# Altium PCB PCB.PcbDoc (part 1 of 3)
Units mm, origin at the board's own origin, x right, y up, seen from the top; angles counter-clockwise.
Board outline 43.18 x 22.86 mm, 6 copper layers (TOP, L2_GND, L3_SIG, L4_PWR, L5_GND, BOTTOM), stack 1.573 mm thick; 127 components, 116 nets, 532 pads, 386 vias.
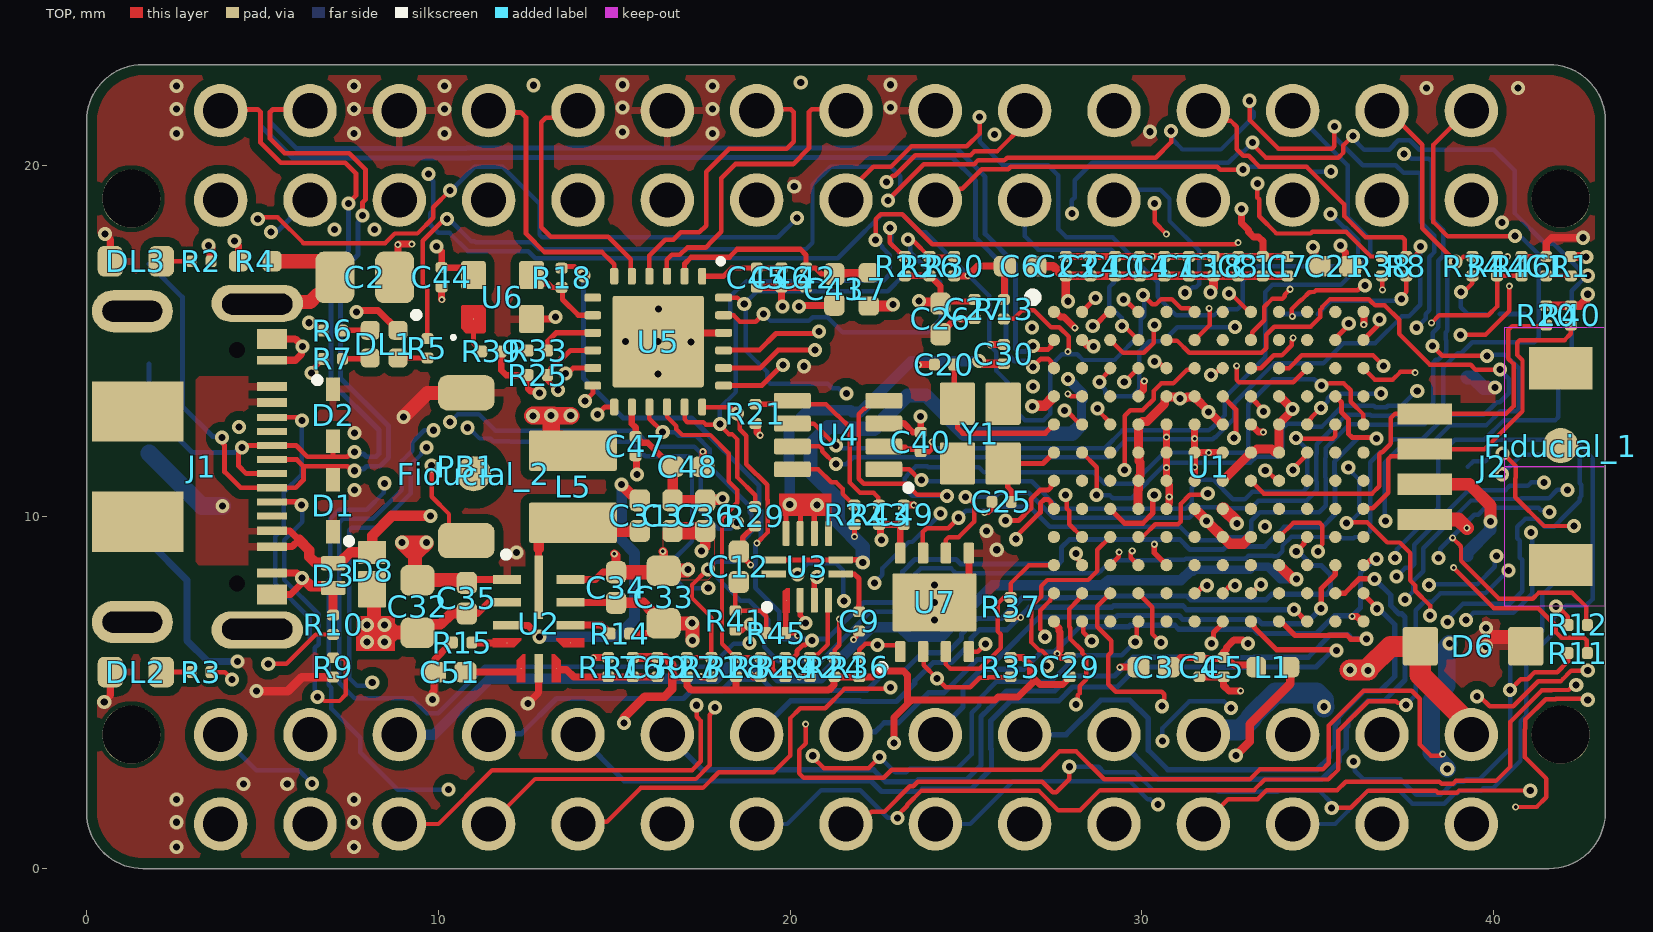
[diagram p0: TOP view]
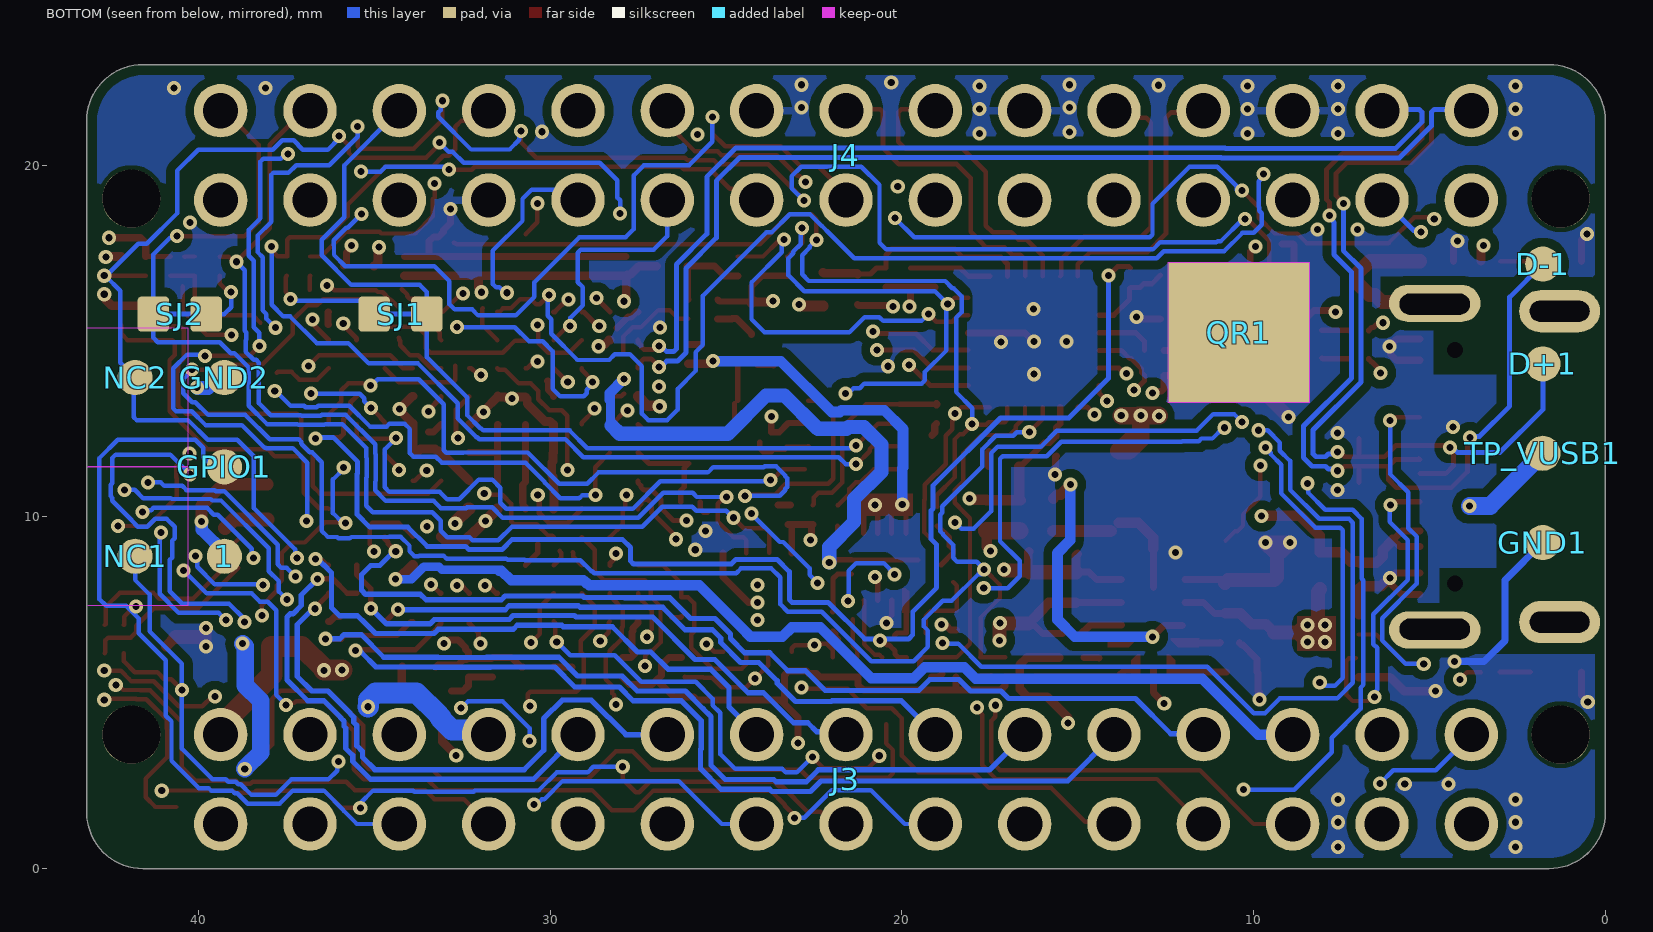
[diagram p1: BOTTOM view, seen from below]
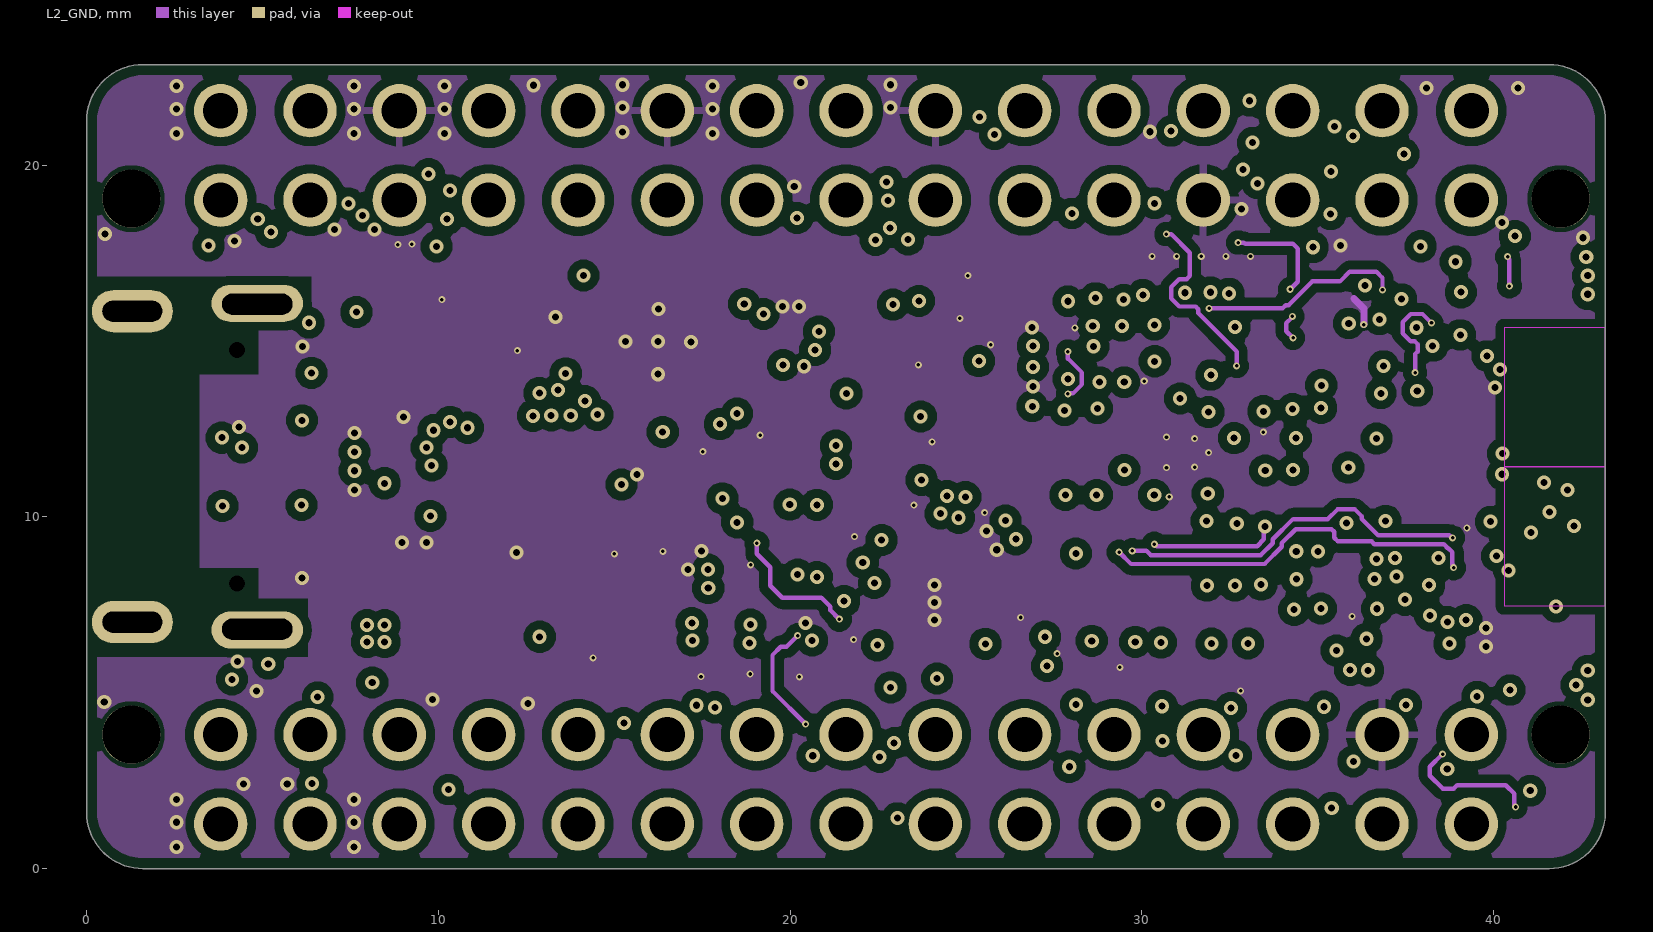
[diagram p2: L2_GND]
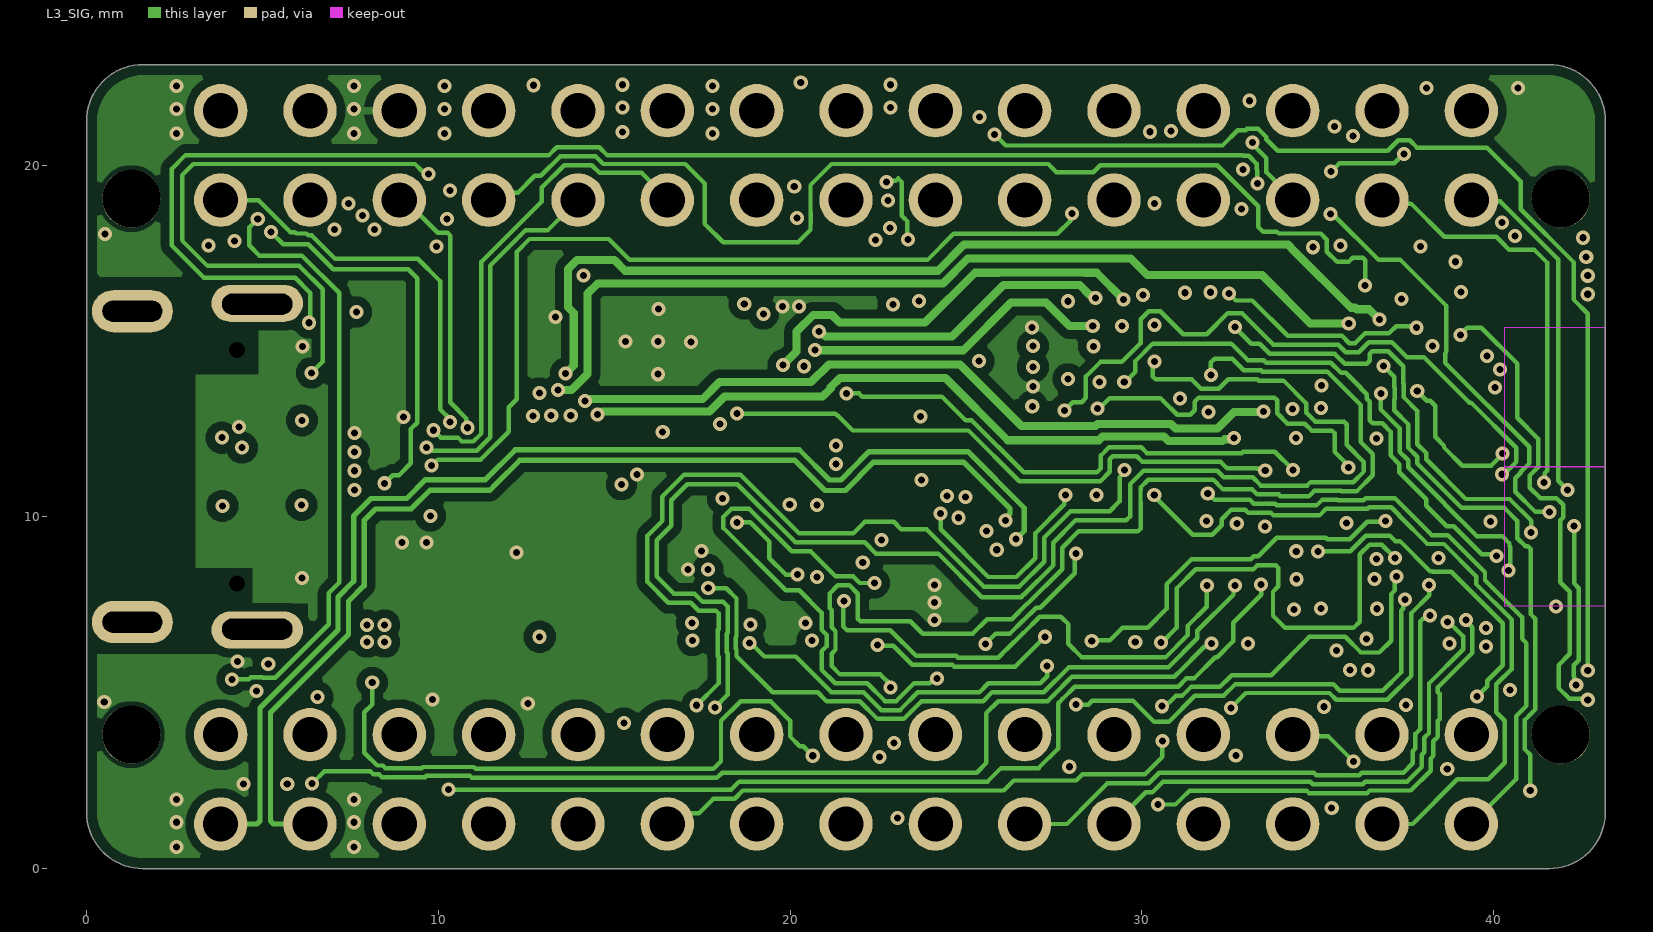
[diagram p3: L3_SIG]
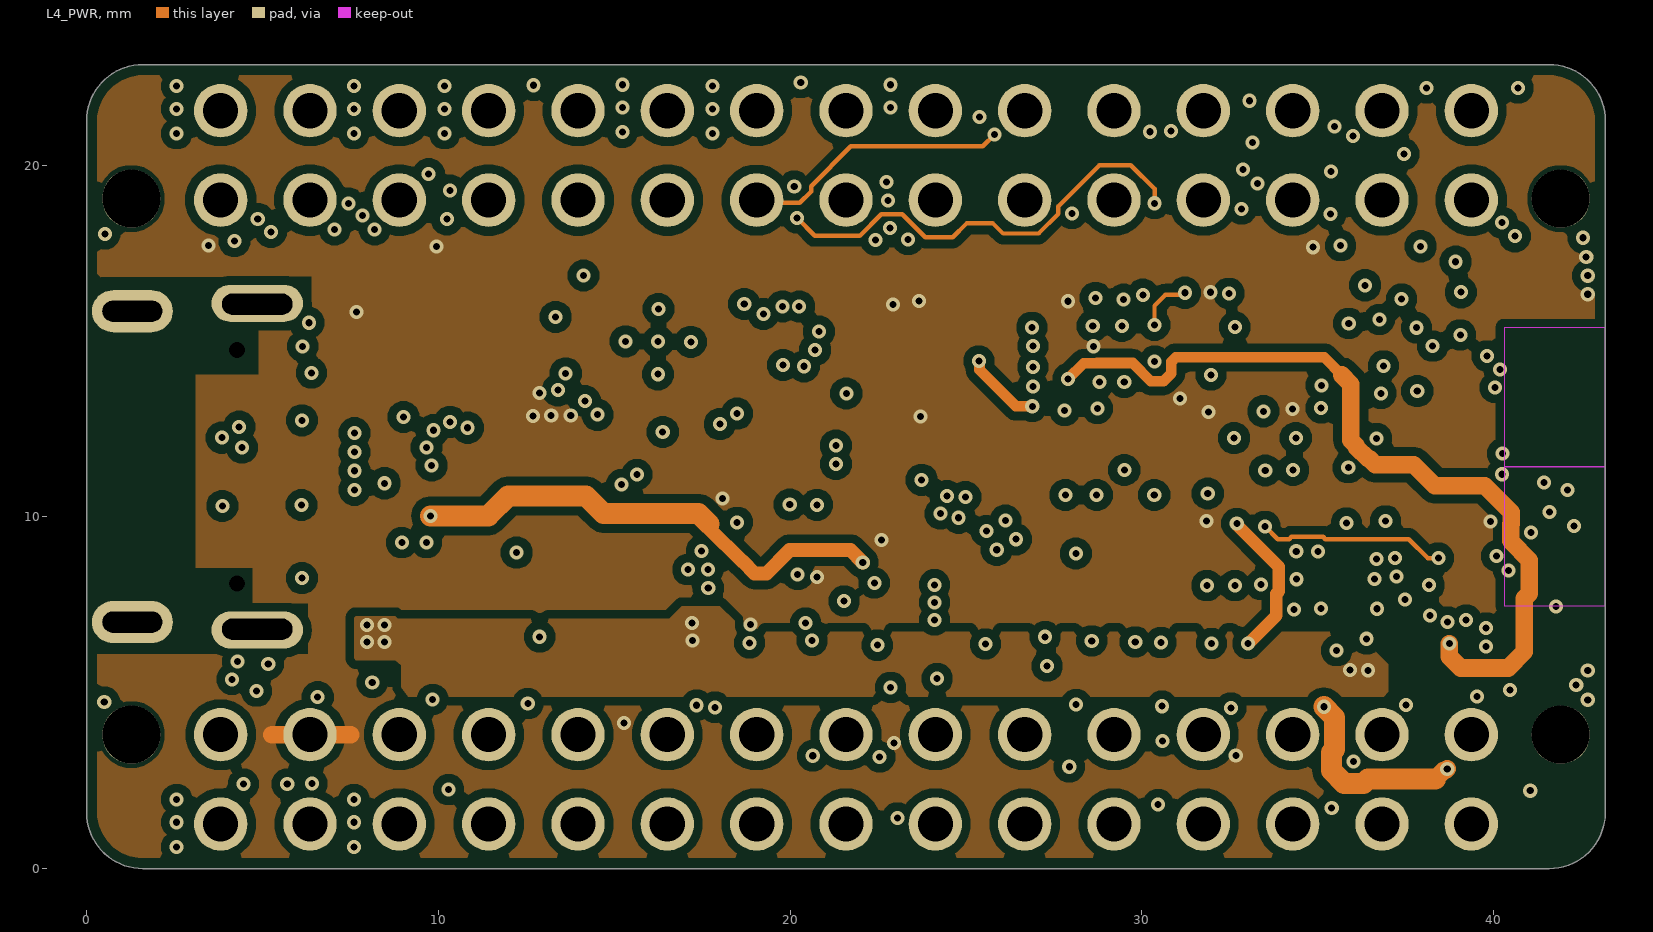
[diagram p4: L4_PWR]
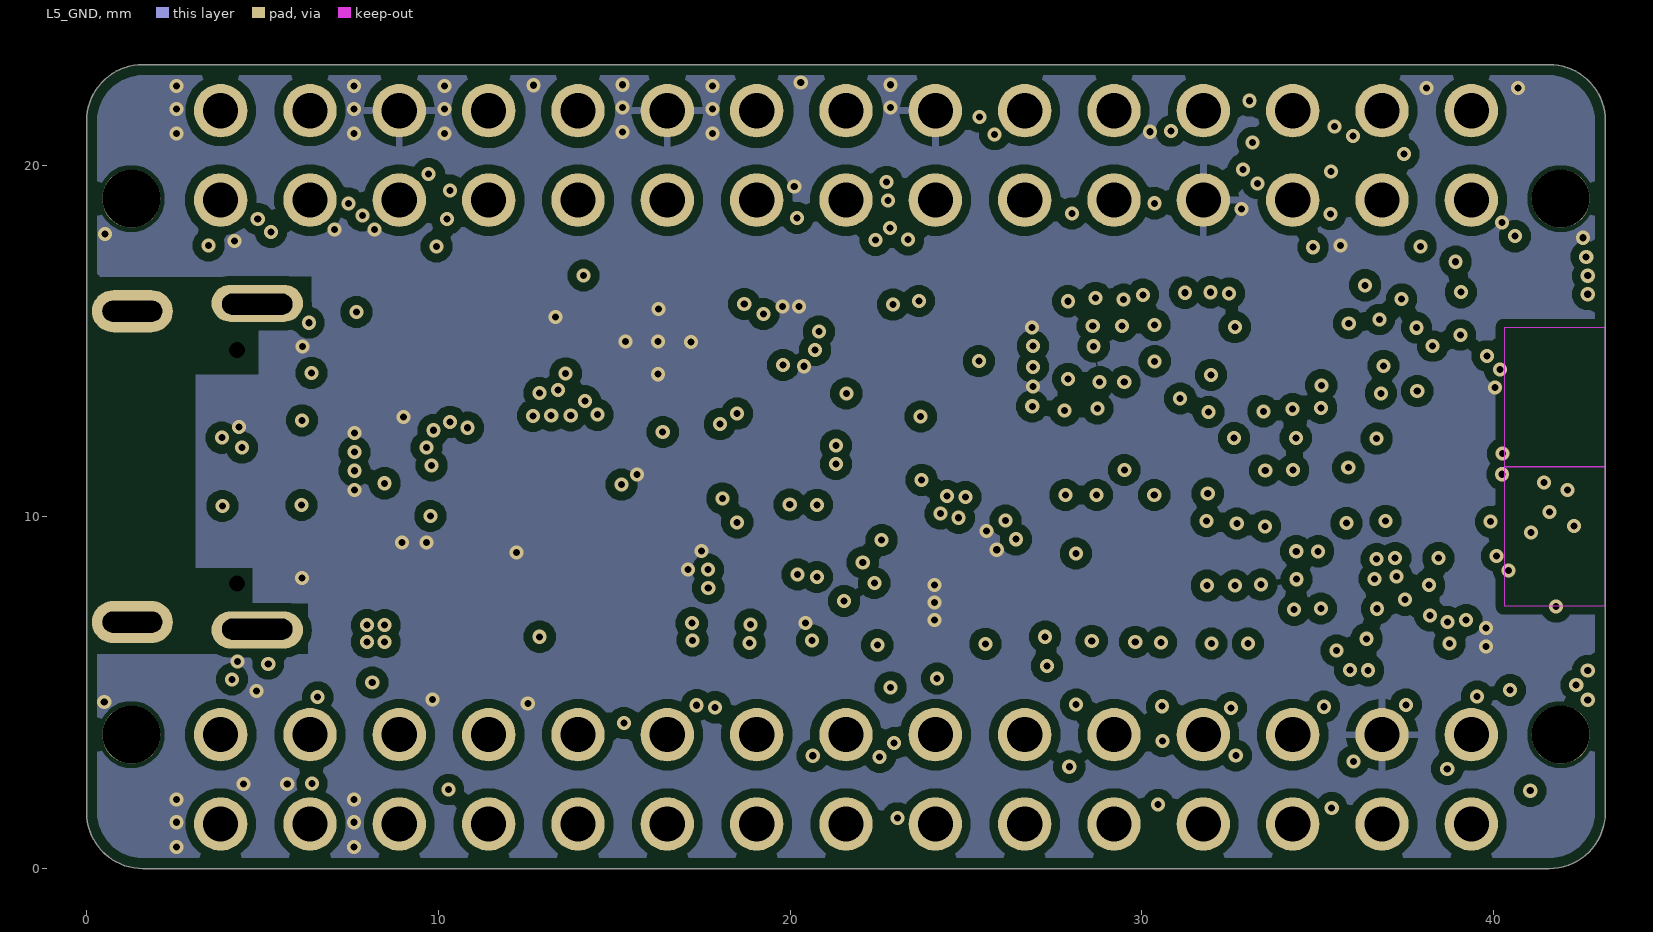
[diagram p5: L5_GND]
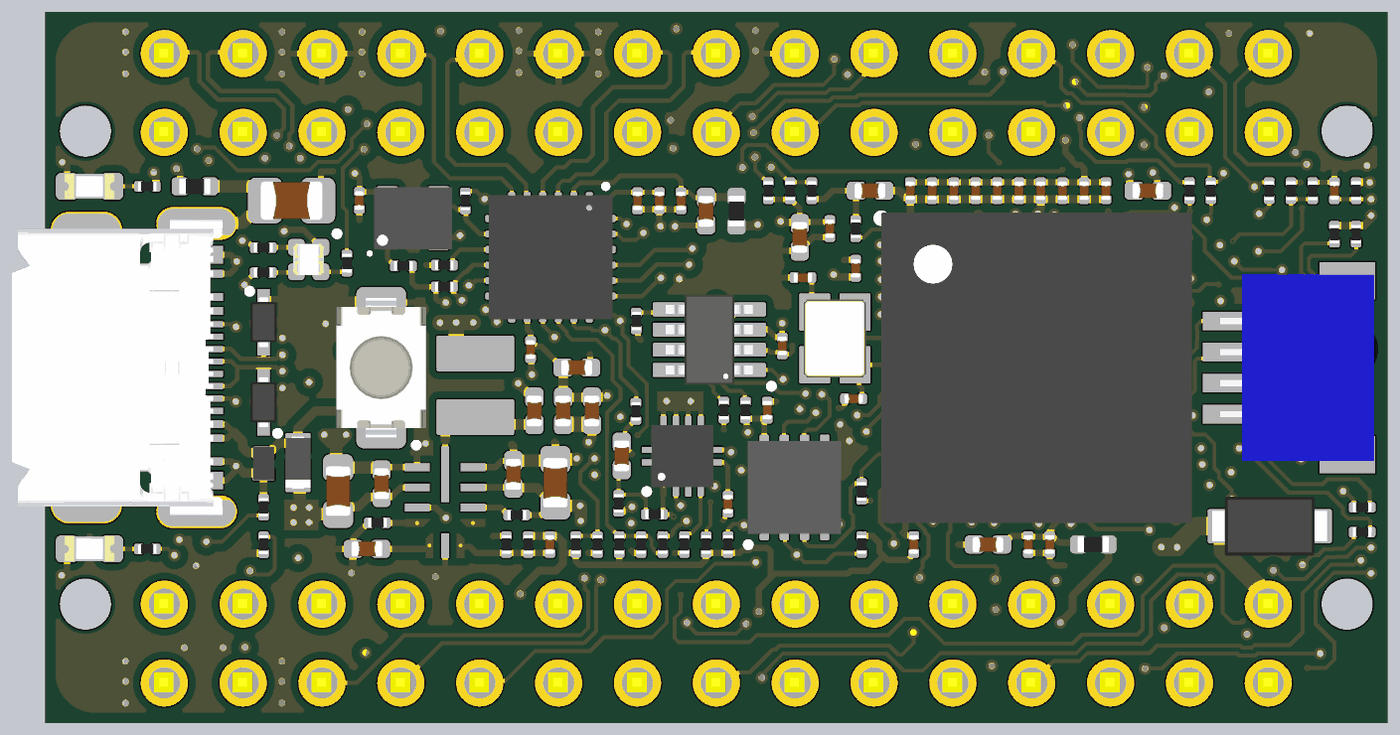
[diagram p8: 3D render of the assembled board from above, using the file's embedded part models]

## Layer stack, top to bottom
Top Solder: solder mask 0.0102, Solder Resist, Dk 3.5
TOP: signal copper 0.0175
Dielectric 1: prepreg 0.08, PP-008, Dk 4.1
L2_GND: signal copper 0.0175
Dielectric 4: core 0.55, Core-037, Dk 4.8
L3_SIG: signal copper 0.0175
Dielectric 2: prepreg 0.2083, PP-022, Dk 4.5
L4_PWR: signal copper 0.0175
Dielectric 5: core 0.55, Core-037, Dk 4.8
L5_GND: signal copper 0.0175
Dielectric 3: prepreg 0.08, PP-008, Dk 4.1
BOTTOM: signal copper 0.0175
Board Layer Stack Bottom Solder: solder mask 0.0102, Solder Resist, Dk 3.5

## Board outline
1.6,0 cw(c1.6,1.6) 0,1.6 0,21.26 cw(c1.6,21.26) 1.6,22.86 41.58,22.86 cw(c41.58,21.26) 43.18,21.26 43.18,1.6 cw(c41.58,1.6) 41.58,0

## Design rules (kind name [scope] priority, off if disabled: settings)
BoardOutlineClearance BoardOutlineClearance_2 [Component = 'J1'] p1: gap=0.1 ignorepadtopadclearanceinfootprint=FALSE
BoardOutlineClearance BoardOutlineClearance_1 [(ObjectKind = 'Pad') And (Name = 'Free-2') And (PadShape_AllLayers = 'Rounded Rectangle') And (AsMM(PadXSize_AllLayers) = 1.3) And (AsMM(PadYSize_AllLayers) = 1.8)] p2: gap=0.1 ignorepadtopadclearanceinfootprint=FALSE
BoardOutlineClearance HeadersCastellated [((ObjectKind = 'Pad') And (Component = 'JP1')) OR                                                                                    ((ObjectKind = 'Pad') And (Component = 'JP2'))] p3: gap=0 ignorepadtopadclearanceinfootprint=FALSE
BoardOutlineClearance Silks [(OnLayer('Top Overlay') OR OnLayer('Bottom Overlay'))] p4: gap=0 ignorepadtopadclearanceinfootprint=FALSE
BoardOutlineClearance [All] p5: gap=0.3 ignorepadtopadclearanceinfootprint=FALSE
Clearance GND_50R [InNetClass('50R') vs InNet('GND')] p1: gap=0.127 ignorepadtopadclearanceinfootprint=FALSE
Clearance GND_ETH [InDifferentialPairClass('ETH') vs InNet('GND')] p2: gap=0.3 ignorepadtopadclearanceinfootprint=TRUE
Clearance QR [InComponent('QR1') vs InNet('GND')] p3: gap=0.15 ignorepadtopadclearanceinfootprint=FALSE except(0: Arc-SMDPad Arc-Fill Arc-Poly Arc-Region Track-SMDPad Track-Fill Track-Poly Track-Region SMDPad-SMDPad SMDPad-Fill SMDPad-Poly SMDPad-Region THPad-Fill THPad-Poly THPad-Region Via-Fill Via-Poly Via-Region Fill-Fill Fill-Poly Fill-Region Poly-Poly Poly-Region Region-Region)
Clearance COPPER_0.25mm [All] p4: gap=0.127 ignorepadtopadclearanceinfootprint=FALSE except(0.25: Arc-Fill Arc-Poly Arc-Region Track-Fill Track-Poly Track-Region SMDPad-Fill SMDPad-Poly SMDPad-Region THPad-Fill THPad-Poly THPad-Region Via-Fill Via-Poly Via-Region Fill-Fill Fill-Poly Fill-Region Poly-Poly Poly-Region Region-Region)
Clearance "Generic clearance 0.127mm" [All] p5: gap=0.127 ignorepadtopadclearanceinfootprint=TRUE
ComponentClearance TP2 [((Name = 'MTDI') OR (Name = 'MTDO') OR (Name = 'MTCK') OR (Name = 'MTMS'))] p1: gap=-2 collisioncheckmode=3 verticalgap=0 showdistances=FALSE
ComponentClearance TP [HasFootprint('TP-1.00MM') vs HasFootprint('TP-1.00MM')] p2: gap=0.2 collisioncheckmode=3 verticalgap=-10 showdistances=FALSE
ComponentClearance UFL_ANTENNA [InComponent('ANT1') vs HasFootprint('U.FL-R-SMT-1(60)-1')] p3: gap=-20 collisioncheckmode=3 verticalgap=-20 showdistances=FALSE
ComponentClearance Headers [((Footprint = 'PINHD-1X14_5VF') OR (Footprint = 'PINHD-1X14_5VF') OR (Footprint = 'LEDC1608X80N-AK') OR (Footprint = 'CX90B-16P-Footprint-1') ) vs ((Footprint = 'PINHD-1X14_5VF') OR (Footprint = 'PINHD-1X14_5VF') OR (Footprint = 'LEDC1608X80N-AK') OR (Footprint = 'CX90B-16P-Footprint-1'))] p4: gap=-20 collisioncheckmode=3 verticalgap=-20 showdistances=FALSE
ComponentClearance RFshield [HasFootprint('Shield RF 10mm x 15mm x 3mm-Footprint-1')] p5: gap=-50 collisioncheckmode=3 verticalgap=-20 showdistances=FALSE
ComponentClearance fiducials [InComponent('Fiducial_1') vs InComponent('PB1')] p6: gap=-20 collisioncheckmode=3 verticalgap=-20 showdistances=FALSE
ComponentClearance [All] p7: gap=0.2 collisioncheckmode=3 verticalgap=0 showdistances=TRUE
DiffPairsRouting USB [InDifferentialPairClass('USB')] p1: maxlimit=0.25 minlimit=0.13 mostfreqgap=0.15 toplayer_maxgap=0.13 toplayer_prefgap=0.13 toplayer_minwidth=0.14 toplayer_maxwidth=0.14 toplayer_prefwidth=0.14 midlayer2_mingap=0.15 midlayer2_maxgap=0.15 midlayer2_minwidth=0.15 midlayer2_maxwidth=0.15 midlayer2_prefwidth=0.15 midlayer3_mingap=0.15 midlayer3_maxgap=0.15 midlayer3_minwidth=0.15 midlayer3_maxwidth=0.15 midlayer3_prefwidth=0.15 bottomlayer_maxgap=0.13 bottomlayer_prefgap=0.13 bottomlayer_minwidth=0.14 bottomlayer_maxwidth=0.14 bottomlayer_prefwidth=0.14 impedanceprofiledriven=TRUE impedanceprofileid={80FA380A-D0E5-4DCC-A5FB-10CACAF929A0} impedanceprofilevalue=90.000000 maxuncoupledlength=12.7
DiffPairsRouting USB_FS [InDifferentialPairClass('USBC_FS')] p2: maxlimit=0.25 minlimit=0.13 mostfreqgap=0.15 toplayer_maxgap=0.13 toplayer_prefgap=0.13 toplayer_minwidth=0.14 toplayer_maxwidth=0.14 toplayer_prefwidth=0.14 midlayer2_mingap=0.15 midlayer2_maxgap=0.15 midlayer2_minwidth=0.15 midlayer2_maxwidth=0.15 midlayer2_prefwidth=0.15 midlayer3_mingap=0.15 midlayer3_maxgap=0.15 midlayer3_minwidth=0.15 midlayer3_maxwidth=0.15 midlayer3_prefwidth=0.15 bottomlayer_maxgap=0.13 bottomlayer_prefgap=0.13 bottomlayer_minwidth=0.14 bottomlayer_maxwidth=0.14 bottomlayer_prefwidth=0.14 impedanceprofiledriven=TRUE impedanceprofileid={80FA380A-D0E5-4DCC-A5FB-10CACAF929A0} impedanceprofilevalue=90.000000 maxuncoupledlength=12.7
DiffPairsRouting ETH [InDifferentialPairClass('ETH')] p3: maxlimit=0.3 minlimit=0.15 mostfreqgap=0.25 toplayer_mingap=0.3 toplayer_prefgap=0.3 toplayer_minwidth=0.133 toplayer_maxwidth=0.133 toplayer_prefwidth=0.133 midlayer2_mingap=0.218 midlayer2_maxgap=0.218 midlayer2_prefgap=0.218 midlayer2_minwidth=0.15 midlayer2_maxwidth=0.15 midlayer2_prefwidth=0.15 midlayer3_mingap=0.218 midlayer3_maxgap=0.218 midlayer3_prefgap=0.218 midlayer3_minwidth=0.15 midlayer3_maxwidth=0.15 midlayer3_prefwidth=0.15 bottomlayer_mingap=0.3 bottomlayer_prefgap=0.3 bottomlayer_minwidth=0.133 bottomlayer_maxwidth=0.133 bottomlayer_prefwidth=0.133 impedanceprofiledriven=TRUE impedanceprofileid={95B8D7AC-9C73-46F7-8235-481973D37AAE} impedanceprofilevalue=100.000000 maxuncoupledlength=12.7
Height [All] p1: minheight=0 maxheight=30 prefheight=12.7
HoleSize [All] p1: absolutevalues=TRUE maxlimit=30 minlimit=0.099 maxpercent=80.000 minpercent=20.000
HoleToHoleClearance [All] p1: gap=0.25 allowstackedmicrovias=FALSE
MatchedLengths RMII_TX [InNet('TXDI') AND InNet('TXD0')] p1: tolerance=1.25 checknetsindiffpair=FALSE checkdiffpairvsdiffpair=TRUE checkxsignals=TRUE checkothers=TRUE phasematching=TRUE phasetolerance=0.254 phasedistance=12.7
MatchedLengths RMII_RX [InNet('RXD1') AND InNet('RXD0')] p2: tolerance=1.25 checknetsindiffpair=FALSE checkdiffpairvsdiffpair=TRUE checkxsignals=TRUE checkothers=TRUE phasematching=TRUE phasetolerance=0.254 phasedistance=12.7
MatchedLengths ETH_intra [InDifferentialPairClass('ETH')] p3: tolerance=0.25 checknetsindiffpair=TRUE checkdiffpairvsdiffpair=FALSE checkxsignals=FALSE checkothers=FALSE phasematching=TRUE phasetolerance=0.254 phasedistance=12.7
MatchedLengths ETH_group [InDifferentialPairClass('ETH')] p4: tolerance=50 checknetsindiffpair=FALSE checkdiffpairvsdiffpair=TRUE checkxsignals=TRUE checkothers=TRUE
NetAntennae NetAntennae_SJ [InComponent('SJ1') OR InComponent('SJ2')] p1: netantennaetolerance=1
NetAntennae [All] p2: netantennaetolerance=0
PlaneConnect [All] p1: pad.planeconnectstyle=Relief pad.reliefexpansion=0.508 pad.reliefentries=4 pad.reliefconductorwidth=0.15 pad.reliefairgap=0.254 via.planeconnectstyle=Direct via.reliefexpansion=0.508 via.reliefentries=4 via.reliefconductorwidth=0.254 via.reliefairgap=0.254
PolygonConnect 0201 [HasFootprint('RES-0201') OR HasFootprint('CAP-0201')] p1: connectstyle=Relief reliefconductorwidth=0.15 reliefentries=4 polygonreliefangle="90 Angle" airgapwidth=0.254
PolygonConnect PolygonConnect_QR [HasFootprint('QR CODE 4x4mm') vs InNet('GND')] p2: connectstyle=Direct reliefconductorwidth=0.2 reliefentries=4 polygonreliefangle="90 Angle" airgapwidth=0.254
PolygonConnect [All] p3: thpad.connectstyle=Relief thpad.reliefconductorwidth=0.2 thpad.reliefentries=4 thpad.polygonreliefangle="90 Angle" thpad.airgapwidth=0.254 smdpad.connectstyle=Relief smdpad.reliefconductorwidth=0.2 smdpad.reliefentries=4 smdpad.polygonreliefangle="90 Angle" smdpad.airgapwidth=0.254 via.connectstyle=Direct via.reliefconductorwidth=0.254 via.reliefentries=4 via.polygonreliefangle="90 Angle" via.airgapwidth=0.254
RoomDefinition TOP [InComponentClass('TOP')] p1: confinementstyle=ConfineIn formatcopy=TRUE lockcomponents=FALSE outline 44.6,5.14 48.6,5.14 48.6,8.14 44.6,8.14
RoutingVias BlindVias [IsBlindVia] p1: holewidth=0.1 width=0.2 viastyle="Through Hole" minholewidth=0.09 minwidth=0.19 maxholewidth=0.1 maxwidth=0.2
RoutingVias StandardVias [All] p2: holewidth=0.2 width=0.4 viastyle="Through Hole" minholewidth=0.2 minwidth=0.4 maxholewidth=0.2 maxwidth=0.4
ShortCircuit ShortCircuit_jumper1 [Component = 'SJ1' vs (InNet('CANL_1') OR InNet('NetR8_1'))] p1: allowed=TRUE
ShortCircuit ShortCircuit_jumper2 [Component = 'SJ2' vs (InNet('RS485 B_1') OR InNet('NetR34_1'))] p2: allowed=TRUE
ShortCircuit [Component = 'SJ1' vs (InNet('+3V3') OR InNet('NetC25_2'))] p3: allowed=TRUE
SilkToSilkClearance [All] p1: silktosilkclearance=0.2
SilkToSolderMaskClearance [IsPad] p1: minsilkscreentomaskgap=0.15 clearancetoexposedcopper=TRUE
SolderMaskExpansion VIAtented [IsVia] p1: expansion=0.102 istentingtop=TRUE
SolderMaskExpansion [All] p2: expansion=0.05 istentingtop=FALSE
SupplyNets "Schematic Supply Nets" [InNet('VIN')] p1: voltage=0.000
SupplyNets "Schematic Supply Nets_6" [InNet('+VBUS')] p2: voltage=0.000
SupplyNets "Schematic Supply Nets_3" [InNet('GND')] p3: voltage=0.000
SupplyNets "Schematic Supply Nets_1" [InNet('+3V3')] p4: voltage=0.000
UnConnectedPin [All] p1:
UnRoutedNet [All] p1: checkbadconnections=TRUE
ViasUnderSMD Flash [(ObjectKind = 'Pad') And (Name = 'U2-9')] p1: allowed=TRUE
ViasUnderSMD uC [(ObjectKind = 'Pad') And (Name = 'U4-49')] p2: allowed=TRUE
ViasUnderSMD [All] p3: allowed=FALSE
Width 50R [InNetClass('RMII')] p1: maxlimit=0.231 minlimit=0.099 preferedwidth=0.231 toplayer_minwidth=0.142 toplayer_maxwidth=0.142 toplayer_prefwidth=0.142 midlayer1_maxwidth=0.099 midlayer1_prefwidth=0.099 midlayer2_minwidth=0.231 midlayer3_minwidth=0.231 midlayer4_maxwidth=0.099 midlayer4_prefwidth=0.099 bottomlayer_minwidth=0.142 bottomlayer_maxwidth=0.142 bottomlayer_prefwidth=0.142 impedanceprofiledriven=TRUE impedanceprofileid={20FD7761-1233-4024-A355-2B769554217A} impedanceprofilevalue=50.000000 minimp=50.000000 maximp=50.000000 favimp=50.000000
Width StandardTraces [All] p2: maxlimit=5 minlimit=0.127 preferedwidth=0.15
19 further rules are at their usual default settings.

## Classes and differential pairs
differential pair class USB: USB_D_1
differential pair class ETH: ETH_RX_1 ETH_TX_1
differential pair class USBC_FS: USBFS_D
net class ETH: ETH_RX_1_N ETH_RX_1_P ETH_TX_1_N ETH_TX_1_P
net class RMII: MDC MDIO RXD0 RXD1 TXD0 TXDI TXEN
component class "U_UART - RS485": + C49 R35 R36 R37 U7
component class U_MICROCONTROLLER: C3 C4 C5 C6 C7 C8 C10 C11 C13 C14 C17 C18 C20 C21 C23 C24 C25 C26 C27 C29 L1 R11 R12 R13 U1 Y1
component class U_ETH_10_100: C42 C43 C44 C45 C46 C47 C48 L7 R23 R24 R25 R26 R27 R28 R29 R30 R31 R32 R33 R39 U5 U6
component class U_CAN_PHY: C40 R21 R22 R43 U4
component class TOP: 1 + C1 C2 C9 C12 C30 C31 C32 C33 C34 C35 C36 C37 C39 C51 D1 D2 D3 D6 D8 D+1 D-1 DL1 DL2 DL3 Fiducial_1 Fiducial_2 GND1 GND2 GPIO1 J1 J2 J3 J4 L5 NC1 NC2 PB1 QR1 R1 R2 R3 R4 R5 R6 R7 R8 R9 R10 R14 R15 R16 R17 R18 R19 R20 R34 R38 R40 R41 R42 R44 R45 R46 SJ1 SJ2 TP_VUSB1 U2 U3
differential pair USB_D_1: +USB_D_1_P -USB_D_1_N
differential pair ETH_TX_1: +ETH_TX_1_P -ETH_TX_1_N
differential pair ETH_RX_1: +ETH_RX_1_P -ETH_RX_1_N
differential pair USBFS_D: +USBFS_D_P -USBFS_D_N

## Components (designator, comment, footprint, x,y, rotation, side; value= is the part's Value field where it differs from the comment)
1 "Test point 1.00mm" TP-1.00MM 39.263,8.881 r270 bottom
C1 "CL03A104KP3NNNC" CAP-0201 41.5,17.131 r270 top value=100nF
C2 "FV21X472K102ECG" CAP-0805 7.908,16.813 r180 top value=4.7nF
C3 "CC0402KRX5R6BB475" CAP-0402 30.341,5.731 r0 top value=4.7µF
C4 "CL03A104KP3NNNC" CAP-0201 31.639,5.731 r90 top value=100nF
C5 "CL03B103KP3NNND" CAP-0201 32.329,5.731 r90 top value=10nF
C6 "GRM158R60J226ME01D" CAP-0402 26.541,17.131 r0 top value=22µF
C7 "CL03A104KP3NNNC" CAP-0201 34.141,17.131 r270 top value=100nF
C8 "CL03A104KP3NNNC" CAP-0201 32.741,17.131 r270 top value=100nF
C9 "CL03B103KP3NNND" CAP-0201 21.965,7.031 r270 top value=10nF
C10 "CL03B103KP3NNND" CAP-0201 29.241,17.131 r270 top value=10nF
C11 "CL03B103KP3NNND" CAP-0201 33.441,17.131 r270 top value=10nF
C12 "CC0402KRX5R6BB475" CAP-0402 18.544,8.586 r270 top value=4.7µF
C13 "CL03A104KP3NNNC" CAP-0201 31.341,17.131 r270 top value=100nF
C14 "CL03A104KP3NNNC" CAP-0201 29.941,17.131 r270 top value=100nF
C17 "CL03B103KP3NNND" CAP-0201 30.641,17.131 r270 top value=10nF
C18 "CL03B103KP3NNND" CAP-0201 32.041,17.131 r270 top value=10nF
C20 "CC0201GRNPO9BN100" CAP-0201 24.377,14.33 r180 top value=10pF
C21 "GRM158R60J226ME01D" CAP-0402 35.491,17.131 r180 top value=22µF
C23 "CL03A104KP3NNNC" CAP-0201 27.841,17.131 r270 top value=100nF
C24 "CL03B103KP3NNND" CAP-0201 28.541,17.131 r270 top value=10nF
C25 "CC0201GRNPO9BN100" CAP-0201 26.013,10.426 r180 top value=10pF
C26 "CC0402KRX5R6BB475" CAP-0402 24.277,15.63 r90 top value=4.7µF
C27 "CL03A104KP3NNNC" CAP-0201 25.245,15.909 r90 top value=100nF
C29 "CL03A104KP3NNNC" CAP-0201 27.949,5.731 r270 top value=100nF
C30 "CL03A104KP3NNNC" CAP-0201 26.077,14.63 r270 top value=100nF
C31 "GRM155R61H104KE19D" CAP-0402 15.728,10.037 r90 top value=100nF
C32 "GRM188R6YA475KE15D" CAP-0603 9.408,7.453 r270 top value=4.7µF
C33 "GRM188R6YA475KE15D" CAP-0603 16.407,7.722 r270 top value=4.7µF
C34 "GRM155R61H104KE19D" CAP-0402 15.053,7.993 r270 top value=100nF
C35 "GRM155R61H104KE19D" CAP-0402 10.809,7.691 r270 top value=100nF
C36 "CC0402KRX5R6BB475" CAP-0402 17.584,10.037 r90 top value=4.7µF
C37 "CC0402KRX5R6BB475" CAP-0402 16.656,10.037 r90 top value=4.7µF
C39 "CC0201JPNPO8BN220" CAP-0201 16.229,5.731 r90 top value=22pF
C40 "CL03A104KP3NNNC" CAP-0201 23.715,12.131 r90 top value=100nF
C42 "CL03A104KP3NNNC" CAP-0201 20.455,16.806 r90 top value=100nF
C43 "GRM158R60J226ME01D" CAP-0402 21.259,16.47 r90 top value=22µF
C44 "CL03A104KP3NNNC" CAP-0201 10.092,16.814 r90 top value=100nF
C45 "CL03A104KP3NNNC" CAP-0201 19.055,16.806 r90 top value=100nF
C46 "CM03X5R225M06AH" CAP-0201 19.755,16.806 r90 top value=2.2µF
C47 "CL03A104KP3NNNC" CAP-0201 15.608,12.013 r90 top value=100nF
C48 "GRM158R60J226ME01D" CAP-0402 17.096,11.43 r180 top value=22µF
C49 "CL03A104KP3NNNC" CAP-0201 23.232,10.06 r270 top value=100nF
C51 "C1005X5R1E105K050BC" CAP-0402 10.336,5.589 r0 top value=1µF
D1 "ESD321DYAR" ESD321DYAR 7.008,10.313 r270 top
D2 "ESD321DYAR" ESD321DYAR 7.008,12.892 r90 top
D3 "STN101050B301" X1-DFN1006-2 7.008,8.333 r270 top
D6 "SJD12C24L01" SOD123W_BIDIR 39.417,6.322 r180 top
D8 "TPMEG4020EPK" "DFN1608-2 TPMEG4020EPK" 8.115,8.469 r270 top
D+1 "Test point 1.00mm" TP-1.00MM 1.778,14.351 r180 bottom locked
D-1 "Test point 1.00mm" TP-1.00MM 1.778,17.191 r180 bottom locked
DL1 "LTST-C28NBEGK-2A" SMLP34RGB2W 8.458,14.913 r180 top
DL2 "LTST-C190KSKT" LEDC1608X80N-AK#1 1.4,5.59 r0 top
DL3 "LTST-C190KGKT" LEDC1608X80N-AK#2 1.4,17.27 r0 top
Fiducial_1 "Fiducial mark 1mm with 2mm solder" "Fiducial mark 1mm with circle-Footprint-1"#1 41.91,12.03 r90 top
Fiducial_2 "Fiducial mark 1mm with 2mm solder" "Fiducial mark 1mm with circle-Footprint-1"#2 11,11.23 r270 top
GND1 "Test point 1.00mm" TP-1.00MM 1.778,9.271 r90 bottom
GND2 "Test point 1.00mm" TP-1.00MM 39.263,13.961 r270 bottom
GPIO1 "Test point 1.00mm" TP-1.00MM 39.263,11.421 r90 bottom
J1 "CX90B-16P" CX90B-16P-Footprint-1 3.288,11.43 r270 top locked
J2 "SM04B-SRSS-TB(LF)(SN)" SM04B-SRSS-TB(LF)(SN)-Footprint-1 39.977,11.43 r270 top locked
J3 "2.54-2*15P" "PIN HEADER MALE 2.54mm VERT. 2x15POS" 21.57,2.56 r0 bottom locked
J4 "2.54-2*15P" "PIN HEADER MALE 2.54mm VERT. 2x15POS" 21.57,20.3 r0 bottom locked
L1 "BLM15PX121SN1D" L-0402 33.729,5.731 r180 top value=120µH
L5 "AOTA-C322512Q100MT" "3225 IND" 13.829,10.861 r90 top
L7 "BLM15PX121SN1D" L-0402 22.241,16.473 r270 top value=120µH
NC1 "Test point 1.00mm" TP-1.00MM 41.803,8.881 r270 bottom
NC2 "Test point 1.00mm" TP-1.00MM 41.803,13.961 r270 bottom
PB1 "IT-1185AP1C-160G-GTR" C&K_PTS820_NO_HOLES-1 10.794,11.43 r270 top locked
QR1 "QR CODE 4x4mm" "QR CODE 4x4mm" 10.425,15.24 r180 bottom
R1 "RC0201FR-075K1L" RES-0201 42.2,17.131 r90 top value=5.1k
R2 "RC0201FR-071KL" RES-0201 3.261,17.27 r0 top value=1k
R3 "RC0201FR-071KL" RES-0201 3.261,5.59 r0 top value=1k
R4 "CRCW04021M00FKED" RES-0402 4.796,17.27 r0 top value=1M
R5 "RC0201FR-075K1L" RES-0201 9.689,14.796 r270 top value=5.1k
R6 "RC0201FR-073KL" RES-0201 6.999,15.296 r0 top value=3k
R7 "RC0201FR-073KL" RES-0201 6.999,14.496 r0 top value=3k
R8 "RC0201FR-07120RL" RES-0201 37.521,17.131 r90 top value=120
R9 "RC0201FR-075K1L" RES-0201 7.008,5.723 r90 top value=5.1k
R10 "RC0201FR-075K1L" RES-0201 7.008,6.933 r270 top value=5.1k
R11 "RC0201FR-0722RL" RES-0201 42.394,6.128 r0 top value=22
R12 "RC0201FR-0722RL" RES-0201 42.394,6.928 r0 top value=22
R13 "RC0201FR-07270RL" RES-0201 26.077,15.905 r90 top value=270
R14 "RC0201FR-071KL" RES-0201 15.163,6.682 r180 top value=1k
R15 "CRCW020115K0FKED" RES-0201 10.675,6.428 r180 top value=15k
R16 "CRCW020147K0FNEDAT" RES-0201 15.529,5.731 r90 top value=47k
R17 "CRCW020115K0FKED" RES-0201 14.829,5.731 r270 top value=15k
R18 "CRCW02010000Z0ED" RES-0201 13.503,16.8 r90 top value=0
R19 "CRCW02010000Z0ED" RES-0201 19.865,5.731 r90 top value=0
R20 "RC0201FR-075K1L" RES-0201 41.5,15.729 r90 top value=5.1k
R21 "RC0201FR-075K1L" RES-0201 19.014,12.931 r270 top value=5.1k
R22 "RC0201FR-075K1L" RES-0201 21.832,10.06 r270 top value=5.1k
R23 "RC0201FR-075K1L" RES-0201 23.265,17.131 r270 top value=5.1k
R24 "RC0201FR-071KL" RES-0201 21.264,5.731 r90 top value=1k
R25 "RC0201FR-071KL" RES-0201 12.829,14.031 r0 top value=1k
R26 "RC0201FR-075K1L" RES-0201 23.965,17.131 r270 top value=5.1k
R27 "RC0201FR-075K1L" RES-0201 17.064,5.731 r270 top value=5.1k
R28 "RC0201FR-075K1L" RES-0201 18.464,5.731 r270 top value=5.1k
R29 "RC0201FR-075K1L" RES-0201 19,10.021 r90 top value=5.1k
R30 "RC0201FR-071KL" RES-0201 24.665,17.131 r270 top value=1k
R31 "RC0201FR-071KL" RES-0201 17.764,5.731 r270 top value=1k
R32 "RC0201FR-071KL" RES-0201 19.164,5.731 r270 top value=1k
R33 "RC0201FR-076K49L" RES-0201 12.829,14.731 r0 top value=6.49k
R34 "RC0201FR-07120RL" RES-0201 39.4,17.131 r90 top value=120
R35 "RC0201FR-075K1L" RES-0201 26.269,5.731 r90 top value=5.1k
R36 "RC0201FR-075K1L" RES-0201 21.964,5.731 r270 top value=5.1k
R37 "RC0201FR-075K1L" RES-0201 26.269,7.44 r90 top value=5.1k
R38 "RC0201FR-075K1L" RES-0201 36.829,17.131 r270 top value=5.1k
R39 "RC0201FR-075K1L" RES-0201 11.51,14.706 r0 top value=5.1k
R40 "RC0201FR-075K1L" RES-0201 42.2,15.731 r90 top value=5.1k
R41 "CRCW020147K0FNEDAT" RES-0201 18.444,7.056 r270 top value=47k
R42 "CRCW020147K0FNEDAT" RES-0201 20.565,5.731 r270 top value=47k
R43 "RC0201FR-075K1L" RES-0201 22.532,10.06 r90 top value=5.1k
R44 "CRCW02010000Z0ED" RES-0201 40.1,17.131 r270 top value=0
R45 "CRCW02010000Z0ED" RES-0201 19.6,6.7 r180 top value=0
R46 "RC0201FR-075K1L" RES-0201 40.8,17.131 r90 top value=5.1k
SJ1 "SOLDER JUMPER CLOSED 0603" "SJ 0603 CLOSED" 34.256,15.769 r180 bottom
SJ2 "SOLDER JUMPER CLOSED 0603" "SJ 0603 CLOSED" 40.533,15.769 r0 bottom
TP_VUSB1 "Test point 1.00mm" TP-1.00MM 1.778,11.811 r90 bottom
U1 "PIC32CK2051SG01144-E/HQB" TFBGA-144 31.902,11.43 r0 top
U2 "MPQ4334GDE-1000-AEC1-Z" MPQ4334GDE-1000-AEC1-Z 12.852,7.097 r0 top
U3 "MP5077GG-Z" "MPS QFN12 2x2mm pitch 0.4mm" 20.489,8.58 r90 top
U4 "TCAN3414DDFR" "SOT-23 Thin 8 pin 2.9 x 2.8mm" 21.365,12.331 r90 top
U5 "KSZ8081RNAIA-TR" "QFN24 TP 2.6mmx2.6mm" 16.25,14.985 r270 top
U6 "DSC1522JI1A-25M00000T" 4-VLGA 11.822,16.25 r0 top
U7 "THVD2410DRBR" DRB0008B 24.107,7.571 r0 top
Y1 "X252012MMB4SI-24" CRYSTAL_2.5x2mm 25.409,12.371 r180 top

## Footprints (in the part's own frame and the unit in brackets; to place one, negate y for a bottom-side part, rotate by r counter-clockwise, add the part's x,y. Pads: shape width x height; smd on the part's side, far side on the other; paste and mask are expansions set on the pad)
4-VLGA [mm]
  round 0.025 smd mask+0.05: 1(-0.825,-0.625)
  rrect19% 0.7x0.8 smd mask+0.05: 2(0.825,-0.625) 3(0.825,0.625) 4(-0.825,0.625)
  silkscreen extent -1.45,-1.19 -1.35,-1.09, body extent -1.25,-1 1.25,1, height 0.81
"3225 IND" [mm] "Chip Inductor, 2-Leads, Body 2,50x2,00mm, IPC Medium Density"
  rrect10% 1.15x2.5 smd mask+0.05: 1(-1.025,0) 2(1.025,0)
  body extent -1.6,-1.25 1.6,1.25, height 1.2
C&K_PTS820_NO_HOLES-1 [mm]
  rrect49% 1x1.6 smd mask+0.05: 1(-2.1,0) 2(2.1,0)
  body extent -2.25,-1.45 2.25,1.45, height 2
CAP-0201 [mm] "Chip Capacitor, 2-Leads, Body 0201 (in) 0603 (mm) IPC Medium Density"
  rrect52% 0.31x0.34 smd mask+0.05: 1(-0.275,0) 2(0.275,0)
  body extent -0.3,-0.15 0.3,0.15, height 0.3
CAP-0402 [mm] "Chip Capacitor, 2-Leads, Body  0402 (in) 1005 (mm), IPC Medium Density"
  rrect52% 0.63x0.58 smd mask+0.05: 1(-0.435,0) 2(0.435,0)
  body extent -0.5,-0.25 0.5,0.25, height 0.5
CAP-0603 [mm] "Chip Capacitor, Body 0603 imperial,1.6x0.8mm, IPC High Density"
  rrect51% 0.87x0.97 smd mask+0.05: 1(-0.75,0) 2(0.75,0)
  body extent -0.8,-0.4 0.8,0.4, height 0.8
CAP-0805 [mm] "Chip Capacitor, Body 0805 imperial, 2.0x1.2mm, IPC Medium Density"
  rrect45% 1.11x1.47 smd mask+0.05: 1(-0.85,0) 2(0.85,0)
  body extent -1,-0.62 1,0.63, height 1.25
CRYSTAL_2.5x2mm [mm]
  rrect10% 1x1.2 smd mask+0.05: 1(-0.65,0.85) 2(-0.65,-0.85) 3(0.65,-0.85) 4(0.65,0.85)
  body extent -1,-1.25 1,1.25, height 0.65
CX90B-16P-Footprint-1 [mm]
  rect 0.57x0.85 smd mask+0.05: A1(-3.635,1.988) A12(3.635,1.988)
  rect 0.25x0.85 smd mask+0.05: A4(-2.275,1.988) A9(2.275,1.988) B1(3.025,1.988) B4(1.825,1.988) B9(-1.825,1.988) B12(-3.025,1.988)
  rect 0.2x0.85 smd mask+0.05: A5(-1.4,1.988) A6(-0.6,1.988) A7(0.6,1.988) A8(1.4,1.988) B5(1,1.988) B6(0.2,1.988) B7(-0.2,1.988) B8(-1,1.988)
  round 0.2 hole 0.45 unplated paste-2539.97 mask+0.2: FIXING(-3.32,0.988) FIXING(3.32,0.988)
  rect 1.71x2.6 smd paste-0.3 mask+0.05: FIXING(-1.565,-1.837) FIXING(1.565,-1.837)
  oval 1.05x2.6 hole 0.6 slot 2 at 90 deg copper offset -0.025,0 mask+0.05: SHIELD1(-4.62,1.563)
  oval 1.05x2.6 hole 0.6 slot 2 at 90 deg copper offset 0.025,0 mask+0.05: SHIELD2(4.62,1.563)
  oval 1.2x2.3 hole 0.6 slot 1.7 at 90 deg mask+0.05: SHIELD3(-4.42,-1.987) SHIELD4(4.42,-1.987)
  body extent -4.77,-4.4 4.77,2.4, height 3.17
"DFN1608-2 TPMEG4020EPK" [mm]
  rrect10% 0.65x0.8 smd paste+0 mask+0.05: A(-0.525,0)
  rrect10% 1.05x0.8 smd paste+0 mask+0.05: C(0.525,0)
  body extent -0.74,-0.4 0.94,0.4, height 0.4
DRB0008B [mm] "SON, 8-Leads, Body 3x3mm, Pitch 0.65mm, Thermal Pad 2.4x1.65mm, TI Recommended"
  rrect33% 0.3x0.6 smd: 1(-0.975,-1.4) 2(-0.325,-1.4) 3(0.325,-1.4) 4(0.975,-1.4) 5(0.975,1.4) 6(0.325,1.4) 7(-0.325,1.4) 8(-0.975,1.4)
  rrect6% 2.4x1.65 smd paste-1.2: 9(0,0)
  silkscreen extent -1.54,-1.9 -1.44,-1.8, body extent -1.5,-1.5 1.5,1.5, height 0.96
ESD321DYAR [mm] "ESD321DYAR SOD-523 1.6x0.8mm"
  rect 0.67x0.4 smd mask+0.05: 1(0.74,0) 2(-0.74,0)
  silkscreen extent 0.95,0.4 1.05,0.5, body extent -0.8,-0.43 0.8,0.43, height 0.82
"Fiducial mark 1mm with circle-Footprint-1"#1 [mm]
  round 1 smd paste-10 mask+0.5: 1(0,0)
  TOP pour cut-out: 0,1 0.383,0.924 0.707,0.707 0.924,0.383 1,0 1,0 0.924,-0.383 0.707,-0.707 0.383,-0.924 0,-1 0,-1 -0.383,-0.924 -0.707,-0.707 -0.924,-0.383 -1,0 -1,0 -0.924,0.383 -0.707,0.707 -0.383,0.924 0,1
"Fiducial mark 1mm with circle-Footprint-1"#2 [mm]
  round 1 smd paste-10 mask+0.05: 1(0,0)
  TOP pour cut-out: 0,1 0.383,0.924 0.707,0.707 0.924,0.383 1,0 1,0 0.924,-0.383 0.707,-0.707 0.383,-0.924 0,-1 0,-1 -0.383,-0.924 -0.707,-0.707 -0.924,-0.383 -1,0 -1,0 -0.924,0.383 -0.707,0.707 -0.383,0.924 0,1
L-0402 [mm] "Chip Inductor, 2-Leads, Body 0402 (in)"
  rrect51% 0.55x0.58 smd mask+0: 1(-0.475,0) 2(0.475,0)
  body extent -0.5,-0.25 0.5,0.25, height 0.34
LEDC1608X80N-AK#1 [mm]
  rrect50% 0.72x0.87 smd: A(0.725,0) C(-0.725,0)
  body extent -0.8,-0.4 0.8,0.4, height 0.79
LEDC1608X80N-AK#2 [mm]
  rrect50% 0.72x0.87 smd mask+0.05: A(0.725,0) C(-0.725,0)
  body extent -0.8,-0.4 0.8,0.4, height 0.79
MPQ4334GDE-1000-AEC1-Z [mm]
  rect 0.8x0.25 smd mask+0.05: 1(-0.9,1.125) 2(-0.9,0.475) 3(-0.9,-0.175) 9(0.9,-0.175) 10(0.9,0.475) 11(0.9,1.125)
  round 0.025 smd mask+0.05: 4(-0.9,-0.675) 5(-0.5,-1.4) 7(0.5,-1.4) 8(0.9,-0.675)
  rect 0.25x0.8 smd mask+0.05: 6(0,-1.4)
  rect 0.25x1.8 smd mask+0.05: 12(0,0.9)
  silkscreen extent -0.98,1.78 -0.88,1.88, body extent -1.01,-1.51 1.01,1.51, height 1.02
"MPS QFN12 2x2mm pitch 0.4mm" [mm]
  round 0.025 smd mask+0.05: 1(-0.95,0.6)
  rrect25% 0.7x0.2 smd mask+0.05: 2(-0.95,0.2) 3(-0.95,-0.2) 4(-0.95,-0.6) 7(0.95,-0.6) 8(0.95,-0.2) 9(0.95,0.2) 10(0.95,0.6)
  rrect25% 0.2x0.7 smd mask+0.05: 5(-0.2,-0.95) 6(0.2,-0.95) 11(0.2,0.95) 12(-0.2,0.95)
  silkscreen extent -1.19,1.09 -1.09,1.19, body extent -1,-1 1,1, height 1
"PIN HEADER MALE 2.54mm VERT. 2x15POS" [mm]
  round 1.52 hole 1 mask+0.05: 1(-17.76,-1.25) 2(-17.76,1.29) 3(-15.22,-1.25) 4(-15.22,1.29) 5(-12.68,-1.25) 6(-12.68,1.29) 7(-10.14,-1.25) 8(-10.14,1.29) 9(-7.6,-1.25) 10(-7.6,1.29) 11(-5.06,-1.25) 12(-5.06,1.29) 13(-2.52,-1.25) 14(-2.52,1.29) 15(0.02,-1.25) 16(0.02,1.29) 21(7.64,-1.25) 22(7.64,1.29) 23(10.18,-1.25) 24(10.18,1.29)
  round 1.52 hole 1 paste-2539.97 mask+0.05: 17(2.56,-1.25) 18(2.56,1.29) 19(5.1,-1.25) 20(5.1,1.29) 25(12.72,-1.25) 26(12.72,1.29) 27(15.26,-1.25) 28(15.26,1.29) 29(17.8,-1.25) 30(17.8,1.29)
  body extent -19.05,-2.54 19.05,2.54, height 8.38
"QFN24 TP 2.6mmx2.6mm" [mm] "QFN, 24-Leads, Body 4,00x4,00mm, Pitch 0,50mm, Thermal Pad 2.6mmX2.6mm, IPC Medium Density"
  rrect50% 0.48x0.23 smd mask+0.05: 1(-1.86,1.25) 2(-1.86,0.75) 3(-1.86,0.25) 4(-1.86,-0.25) 5(-1.86,-0.75) 6(-1.86,-1.25) 13(1.86,-1.25) 14(1.86,-0.75) 15(1.86,-0.25) 16(1.86,0.25) 17(1.86,0.75) 18(1.86,1.25)
  rrect50% 0.23x0.48 smd mask+0.05: 7(-1.25,-1.86) 8(-0.75,-1.86) 9(-0.25,-1.86) 10(0.25,-1.86) 11(0.75,-1.86) 12(1.25,-1.86) 19(1.25,1.86) 20(0.75,1.86) 21(0.25,1.86) 22(-0.25,1.86) 23(-0.75,1.86) 24(-1.25,1.86)
  rrect5% 2.6x2.6 smd paste-2.54 mask+0.05: 25(0,0)
  silkscreen extent -2.34,1.73 -2.24,1.83, body extent -1.99,-1.99 1.99,1.99, height 0.89
"QR CODE 4x4mm" [mm]
  rect 4x4 smd paste-2539.97 mask+0: PAD(0,0)
  TOP keep-out region: -2,2 2,2 2,-2 -2,-2
RES-0201 [mm] "Chip Resistor, 2-Leads, Body 0201 (in) 0603 (mm) IPC Medium Density"
  rrect52% 0.31x0.34 smd mask+0.05: 1(-0.275,0) 2(0.275,0)
  body extent -0.3,-0.15 0.3,0.15, height 0.24
RES-0402 [mm] "Chip Resistor, 2-Leads, Body  0402 (in) 1005 (mm), IPC Medium Density"
  rrect51% 0.55x0.58 smd mask+0.05: 1(-0.475,0) 2(0.475,0)
  body extent -0.5,-0.25 0.5,0.25, height 0.34
"SJ 0603 CLOSED" [mm]
  rrect25% 0.9x1 smd paste-2539.97 mask+0.1: 1(0.75,0) 2(-0.75,0)
  TOP lines w0.15: 0.35,0 -0.35,0
SM04B-SRSS-TB(LF)(SN)-Footprint-1 [mm]
  rect 0.6x1.55 smd mask+0.05: 1(1.5,-1.937) 2(0.5,-1.937) 3(-0.5,-1.937) 4(-1.5,-1.937)
  rect 1.2x1.8 smd mask+0.05: FIX(-2.8,1.938) FIX(2.8,1.938)
  body extent -3,-2.15 3,2.8, height 2.98
SMLP34RGB2W [mm]
  rrect52% 0.54x0.54 smd mask+0.05: 1(-0.395,-0.395) 2(-0.395,0.395) 3(0.395,0.395) 4(0.395,-0.395)
  silkscreen extent -0.96,-0.88 -0.86,-0.78, body extent -0.5,-0.5 0.5,0.5, height 0.2
SOD123W_BIDIR [mm] "SODFL, 2-Leads, Body 1,80x3,70mm, IPC Medium Density"
  rrect15% 1x1.1 smd mask+0.05: 1(-1.5,0) 2(1.5,0)
  body extent -1.85,-0.95 1.85,0.95, height 1.02
"SOT-23 Thin 8 pin 2.9 x 2.8mm" [mm]
  rrect25% 0.45x1.05 smd mask+0.05: 1(-0.975,-1.3) 2(-0.325,-1.3) 3(0.325,-1.3) 4(0.975,-1.3) 5(0.975,1.3) 6(0.325,1.3) 7(-0.325,1.3) 8(-0.975,1.3)
  silkscreen extent -1.55,-2.05 -1.45,-1.95, body extent -1.45,-1.4 1.45,1.4, height 1.1
TFBGA-144 [mm] "Body: 10mmx10mmx1.2 mm Pitch: 0.8mm"
  round 0.35 smd mask+0.05: A1(-4.4,4.4) A2(-3.6,4.4) A3(-2.8,4.4) A4(-2,4.4) A5(-1.2,4.4) A6(-0.4,4.4) A7(0.4,4.4) A8(1.2,4.4) A9(2,4.4) A10(2.8,4.4) A11(3.6,4.4) A12(4.4,4.4) B1(-4.4,3.6) B2(-3.6,3.6) B3(-2.8,3.6) B4(-2,3.6) B5(-1.2,3.6) B6(-0.4,3.6) B7(0.4,3.6) B8(1.2,3.6) B9(2,3.6) B10(2.8,3.6) B11(3.6,3.6) B12(4.4,3.6) C1(-4.4,2.8) C2(-3.6,2.8) C3(-2.8,2.8) C4(-2,2.8) C5(-1.2,2.8) C6(-0.4,2.8) C7(0.4,2.8) C8(1.2,2.8) C9(2,2.8) C10(2.8,2.8) C11(3.6,2.8) C12(4.4,2.8) D1(-4.4,2) D2(-3.6,2) D3(-2.8,2) D4(-2,2) D5(-1.2,2) D6(-0.4,2) D7(0.4,2) D8(1.2,2) D9(2,2) D10(2.8,2) D11(3.6,2) D12(4.4,2) E1(-4.4,1.2) E2(-3.6,1.2) E3(-2.8,1.2) E4(-2,1.2) E5(-1.2,1.2) E6(-0.4,1.2) E7(0.4,1.2) E8(1.2,1.2) E9(2,1.2) E10(2.8,1.2) E11(3.6,1.2) E12(4.4,1.2) F1(-4.4,0.4) F2(-3.6,0.4) F3(-2.8,0.4) F4(-2,0.4) F5(-1.2,0.4) F6(-0.4,0.4) F7(0.4,0.4) F8(1.2,0.4) F9(2,0.4) F10(2.8,0.4) F11(3.6,0.4) F12(4.4,0.4) G1(-4.4,-0.4) G2(-3.6,-0.4) G3(-2.8,-0.4) G4(-2,-0.4) G5(-1.2,-0.4) G6(-0.4,-0.4) G7(0.4,-0.4) G8(1.2,-0.4) G9(2,-0.4) G10(2.8,-0.4) G11(3.6,-0.4) G12(4.4,-0.4) H1(-4.4,-1.2) H2(-3.6,-1.2) H3(-2.8,-1.2) H4(-2,-1.2) H5(-1.2,-1.2) H6(-0.4,-1.2) H7(0.4,-1.2) H8(1.2,-1.2) H9(2,-1.2) H10(2.8,-1.2) H11(3.6,-1.2) H12(4.4,-1.2) J1(-4.4,-2) J2(-3.6,-2) J3(-2.8,-2) J4(-2,-2) J5(-1.2,-2) J6(-0.4,-2) J7(0.4,-2) J8(1.2,-2) J9(2,-2) J10(2.8,-2) J11(3.6,-2) J12(4.4,-2) K1(-4.4,-2.8) K2(-3.6,-2.8) K3(-2.8,-2.8) K4(-2,-2.8) K5(-1.2,-2.8) K6(-0.4,-2.8) K7(0.4,-2.8) K8(1.2,-2.8) K9(2,-2.8) K10(2.8,-2.8) K11(3.6,-2.8) K12(4.4,-2.8) L1(-4.4,-3.6) L2(-3.6,-3.6) L3(-2.8,-3.6) L4(-2,-3.6) L5(-1.2,-3.6) L6(-0.4,-3.6) L7(0.4,-3.6) L8(1.2,-3.6) L9(2,-3.6) L10(2.8,-3.6) L11(3.6,-3.6) L12(4.4,-3.6) M1(-4.4,-4.4) M2(-3.6,-4.4) M3(-2.8,-4.4) M4(-2,-4.4) M5(-1.2,-4.4) M6(-0.4,-4.4) M7(0.4,-4.4) M8(1.2,-4.4) M9(2,-4.4) M10(2.8,-4.4) M11(3.6,-4.4) M12(4.4,-4.4)
  silkscreen extent -5.12,4.69 -4.87,4.94, body extent -5,-5 5,5, height 1.2
TP-1.00MM [mm]
  rrect100% 1x1 smd paste-2.54: X(0,0)
X1-DFN1006-2 [mm] "DFN, 2-Leads, Body 0.61x1.01mm, Pitch 0.65mm, IPC High Density"
  rrect25% 0.4x0.7 smd mask+0.05: 1(-0.35,0) 2(0.35,0)
  body extent -0.54,-0.34 0.54,0.34, height 0.53

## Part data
1 D+1 D-1 GND1 GND2 GPIO1 NC1 NC2 TP_VUSB1: library part UT0013-A.6, Manufacturer="This is not a component"
C1 C4 C7 C8 C13 C14 C23 C27 C29 C30 C40 C42 C44 C45 C47 C49: library part C0113-A.8, "CAP CHIP 0201 100nF 10% 10V X5R", Case Code (Imperial)=0201, Dielectric=X5R, Manufacturer="Samsung Electro-Mechanics", Tolerance=10%, Voltage=10V
C2: library part C0059-A.16, "CAP CHIP 0805 4.7nF 10% 1000V X7R", Case Code (Imperial)=0805, Dielectric=X7R, Manufacturer="PSA Shenzen", Manufacturer 2=KEMET, Part number 2=C0805V472KDRACTU, Part number 3=C0805C472KDRACTU, Tolerance=10%, Voltage=1kV
C3 C12 C26 C36 C37: library part C0195-A.3, "CAP CHIP 0402 4.7uF 10% 10V X5R", Case Code (Imperial)=0402, Dielectric=X5R, Manufacturer=YAGEO, Tolerance=10%, Voltage=10V
C5 C9 C10 C11 C17 C18 C24: library part C0205-A.3, "CAP CHIP 0201 10nF 10% 10V X7R", Case Code (Imperial)=0201, Dielectric=X7R, Manufacturer=Samsung, Tolerance=10%, Voltage=10V
C6 C21 C43 C48: library part C0157-A.5, "CAP CHIP 0402 22uF 20% 6.3V X5R", Case Code (Imperial)=0402, Dielectric=X5R, Manufacturer="Murata Electronics", Tolerance=20%, Voltage=6.3V
C20 C25: library part C0144-A.5, "CAP CHIP 0201 10pF 5% 50V C0G", Case Code (Imperial)=0201, Dielectric=C0G, Manufacturer=Yageo, Tolerance=5%, Voltage=50V
C31 C34 C35: library part C0015-A.16, "CAP CHIP 0402 100nF 10% 50V X5R", Case Code (Imperial)=0402, Dielectric=X5R, Manufacturer=Murata, Tolerance=10%, Voltage=50V
C32 C33: library part C0055-A.16, "CAP CHIP 0603 4.7uF 10% 35V X5R", Case Code (Imperial)=0603, Dielectric=X5R, Manufacturer=Murata, Tolerance=10%, Voltage=35V
C39: library part C0115-A.8, "CAP CHIP 0201 22pF 5% 25V C0G", Case Code (Imperial)=0201, Dielectric=C0G, Manufacturer=Yageo, Tolerance=5%, Voltage=25V
C46: library part C0143-A.4, "CAP CHIP 0201 2.2uF 20% 6V3 X5R", Case Code (Imperial)=0201, Dielectric=X5R, Manufacturer="KYOCERA AVX", Tolerance=20%, Voltage=6.3V
C51: library part C0177-A.4, "CAP CHIP 0402 1uF 10% 25V X5R", Case Code (Imperial)=0402, Dielectric=X5R, Manufacturer=TDK, Tolerance=10%, Voltage=25V
D1 D2: library part P0022-5, "TVS 1CH, 30kV, USB 2.0 ETH 10/100/1000, 0-3.6V, 0.9pF, IEC61000-4-5 peak current 80A surge 40W 6A, DC breakdown min 4.5V, SOD523 1.6x0.8mm", Manufacturer="Texas Instruments"
D3: library part D0095-2, "TVS BIDIRECTIONAL SMD Vr = 5V, Vbr min =  5.5V, 300W, DFN1006-2", Manufacturer="Eaton Electronics", Power max=300W
D6: library part D0106-4, "TVS BIDIRECTIONAL SMD Vr = 24V, Vbr min =  26.7V, Vcl = 38.9V, Ileakage = 1uA, 200W, SOD-123", Manufacturer=YAGEO, Power max=200W
D8: library part D0105-1, "DIODE SCHOTTKY SMD 2A 40V DFN1608-2", LCSC part=C22358693, Manufacturer="TECH PUBLIC", Power max=415mW
DL1: library part L0014-A.13, "LED RGB DIFFUSED PICOLED SMD", Case Code (Imperial)=0404, Color=Blue,Green,Red, Forward Current=20mA, Forward Voltage=3V, Lens Color=White, Manufacturer=Liteon, Max Operating Temperature=85°C, Min Operating Temperature=-40°C, Test Current=5mA
DL2: library part L0008-A.6, "LED SMD 0603 GIA588   8mcd 120^", Manufacturer=Liteon
DL3: library part L0009-A.6, "LED SMD 0603 GREEN/568 15mcd 120^", Manufacturer=Liteon
Fiducial_1 Fiducial_2: library part UT0024-A.6
J1: library part J0272-A.3, "CONN RCPT USB3.1 TYPEC 16POS SMD", Manufacturer=Hirose
J2: library part J0005-A.3, "CONN JST SH 1mm 4POS HORIZONTAL TIN QWIIC", LCSC Part #=C160404, Manufacturer=JST
J3 J4: library part J0592-A.5, "HEADER TH 2.54mm VERT. 2x015POS MALE 6mm pin height", LCSC part=C56496, Manufacturer=BOOMELE
L1 L7: library part I0028-A.10, "FERRITE SMD 0402 120Ohm 25% 100MHz Ferrite 2A", Case Code (Imperial)=0402, Case Code (Metric)=1005, Current=2A, DC Resistance (DCR)=55mR, Inductance=120µH, Manufacturer=Murata, Max Operating Temperature=125°C, Min Operating Temperature=-55°C, Package Quantity=10000, Test Frequency=100MHz, Tolerance=25%
L5: library part I0131-A.1, "IND FIXED 10uH 210mR Idc:1.8A Isat:2.3A 3.2 x 2.5 x 1.2mm", Case Code (Metric)=3225, Inductance=10µH, Manufacturer=ABRACON, Max Operating Temperature=155°C, Resonant frequency=1MHz, Tolerance=20%
PB1: library part B0001-A.7, "PUSHBUTTON WHITE NO ANCHORS", Color=White, Manufacturer=Switronic
QR1: library part QR-0001-A.5, "QR CODE 4x4mm on layer 34 (This is not a component)", Manufacturer="This is not a component"
R1 R5 R9 R10 R20 R21 R22 R23 R26 R27 R28 R29 R35 R36 R37 R38 R39 R40 R43 R46: library part R0169-A.26, "RES CHIP 0201 5k1 1% 1/20W", Case Code (Imperial)=0201, Manufacturer=Yageo, Manufacturer 2=Panasonic, Part number 2=ERJ-1GNF5101C, Power=50mW, Temperature coefficient=200ppm, Tolerance=1%
R2 R3 R14 R24 R25 R30 R31 R32: library part R0195-A.23, "RES CHIP 0201 1k 1% 1/20W", Case Code (Imperial)=0201, Manufacturer=Yageo, Power=50mW, Temperature coefficient=200ppm, Tolerance=1%
R4: library part R0058-A.25, "RES CHIP 0402 1M 1% 1/16W", Case Code (Imperial)=0402, Manufacturer=Vishay, Power=62.5mW, Temperature coefficient=100ppm, Tolerance=1%
R6 R7: library part R0416-A.2, "RES CHIP 0201 3k 1% 1/20W", Case Code (Imperial)=0201, Manufacturer=YAGEO, Power=50mW, Temperature coefficient=200ppm, Tolerance=1%
R8 R34: library part R0306-A.2, "RES CHIP 0201 120R 1% 1/20W", Case Code (Imperial)=0201, Manufacturer=YAGEO, Power=50mW, Temperature coefficient=200ppm, Tolerance=1%
R11 R12: library part R0228-A.17, "RES CHIP 0201 22R 1% 1/20W", Case Code (Imperial)=0201, Manufacturer=Yageo, Power=50mW, Temperature coefficient=200ppm, Tolerance=1%
R13: library part R0407-A.2, "RES CHIP 0201 270R 1% 1/20W", Case Code (Imperial)=0201, Manufacturer=YAGEO, Power=50mW, Temperature coefficient=200ppm, Tolerance=1%
R15 R17: library part R0213-A.19, "RES CHIP 0201 15k 1% 1/20W", Case Code (Imperial)=0201, Manufacturer=Vishay, Power=50mW, Temperature coefficient=100ppm, Tolerance=1%
R16 R41 R42: library part R0413-A.2, "RES CHIP 0201 47k 1% 1/20W", Case Code (Imperial)=0201, Manufacturer=Vishay, Power=50mW, Temperature coefficient=200ppm, Tolerance=1%
R18 R19 R44 R45: library part R0140-A.22, "RES CHIP 0201 0R", Case Code (Imperial)=0201, Manufacturer=Vishay, Power=50mW, Temperature coefficient=0ppm, Tolerance=0%
R33: library part R0410-A.2, "RES CHIP 0201 6.49k 1% 1/20W", Case Code (Imperial)=0201, Manufacturer=YAGEO, Power=50mW, Temperature coefficient=200, Tolerance=1%
SJ1 SJ2: library part UT0039-A.4
U1: library part U0591-A.1, "IC Arm Cortex-M33 MCU with 2 MB Flash/512 KB SRAM 144-Pin -40° to 125° TFBGA", Manufacturer="Microchip Technology"
U2: library part U0537-A.2, "IC BUCK Vin 36V, Vout ADJ, Iout 1A, synchronous 65mR/45mR, 2.5MHz, QFN12 2x3mm", Manufacturer=MPS
U3: library part U0512-A.2, "IC Load Switch Vload 0.5V to 5.5V, 10mR at 5V, max 7A, programmable overcurrent limit, linear ramp control, logic ON 1.7V, VCC 3V to 5.5V, -40 to 125°C, QFN12 2x2mm", Manufacturer=MPS
U4: library part U0540-A.4, "IC CAN FD PHY up to 8Mbps, 3V3 VCC, Shut Down mode, Undervoltage protection, SOT-23 2.9 x 2.8mm", Manufacturer="Texas Instruments"
U5: library part U0588-A.1, "IC 10BASE-T/100BASE-TX PHY with RMII 25MHz mode default (Temp: –40C to +85C)", Manufacturer=Microchip, Max Temp=+85, Min Temp=-40
U6: library part X0034-A.2, "IC MEMS OSC 25MHz 50PPM VDD 2.25V - 3.63V  25MHz 2.5 mm x 2.0 mm 4-Lead VLGA", Frequency=25MHz, Frequency Stability=50ppm, Manufacturer="Microchip Technology", Max Operating Temperature=85°C, Max Supply Current=7.5mA, Min Operating Temperature=-40°C
U7: library part U0544-A.2, "IC RS-485 Transceiver ±70-V Fault-Protected 3.3-V to 5-V 500kbps VSON 3mm x 3 mm", Manufacturer="Texas Instruments"
Y1: library part X0038-A.1, "CRYSTAL 12MHz 10pF SMD 2.5 x 2mm", Frequency=12MHz, Frequency Stability=20ppm, Frequency Tolerance=10ppm, LCSC part=C2896601, Load Capacitance=10pF, Manufacturer="YXC Crystal Oscillators", Max Operating Temperature=85°C, Min Operating Temperature=-40°C

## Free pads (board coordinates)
  round 1.651 hole 1.651 unplated: MH(1.27,3.81) MH(1.27,19.05) MH(41.91,3.81) MH(41.91,19.05)

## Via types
v1: diameter 0.4, hole 0.2, TOP to BOTTOM, tented both sides, 318 vias
v2: diameter 0.2, hole 0.1, TOP to L2_GND, tented both sides, 68 vias

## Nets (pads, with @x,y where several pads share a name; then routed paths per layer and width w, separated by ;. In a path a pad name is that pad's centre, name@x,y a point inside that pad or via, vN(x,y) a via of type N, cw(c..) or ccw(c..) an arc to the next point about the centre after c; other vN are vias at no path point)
+3V3: 1.X C6.2 C7.2 C8.2 C10.2 C11.2 C13.2 C14.2 C17.2 C18.2 C21.2 C23.2 C24.2 C26.2 C27.2 C29.2 C36.2 C37.2 C39.2 C40.2 C44.2 C47.2 C48.2 C49.2 DL1.1 J2.2 J3.3 L1.1 L5.2 L7.2 R1.2 R2.2 R16.2 R20.2 R23.2 R24.1 R25.1 R26.2 R27.2 R28.2 R35.2 R36.2 R39.2 R40.2 R41.2 R43.1 U1.B2 U1.D5 U1.D6 U1.D9 U1.E4 U1.E7 U1.E9 U1.F4 U1.F8 U1.F9 U1.G4 U1.G7 U1.H4 U1.H6 U1.J7 U1.J8 U3.3 U4.3 U5.14 U6.4 U7.8 | length 74.6
  TOP w0.15: U3.3@20.689,7.634 20.689,8.154 20.76,8.226 v1(20.76,8.294)
  TOP w0.18: v1(9.947,17.69) 9.96,17.69 10.092,17.558 C44.2@10.092,17.089 10.784,17.089 U6.4@10.997,16.875 ; R39.2@11.785,14.706 11.785,14.175 11.929,14.031 12.554,14.031 12.554,13.64 12.618,13.576 12.672,13.576 12.678,13.57 12.833,13.57 v1(12.875,13.528) ; U5.14@15.5,13.125 15.5,12.651 15.608,12.543 C47.2@15.608,12.288 15.623,12.288 15.801,12.11 15.956,12.11 16.636,11.43 C48.2@16.661,11.43 ; U4.3@22.665,12.656 22.682,12.673 23.223,12.673 23.491,12.406 C40.2@23.715,12.406 v1(23.714,12.858) ; U7.8@23.132,8.971 C49.2@23.133,9.783 ; R23.2@23.265,16.856 R26.2@23.965,16.856 23.98,16.856 24.277,16.558 C26.2@24.277,16.065 24.337,16.125 25.185,16.125 C27.2@25.245,16.184 ; 27.75,5.234 C29.2@27.972,5.456
  TOP w0.2: v1(7.67,15.825) 7.708,15.864 7.85,15.864 7.859,15.873 8.287,15.873 DL1.1@8.853,15.308 ; 16.741,5.456 R27.2@17.064,5.456 17.064,5.201 17.191,5.074 17.548,5.074 18.419,5.074 ; R41.2@18.444,6.781 18.614,6.781 18.738,6.905 18.835,6.905 v1(18.873,6.943) ; R28.2@18.464,5.456 18.464,5.119 18.42,5.074 ; R24.1@21.252,5.456 21.252,5.227 21.099,5.074 18.948,5.074 18.42,5.074 ; R24.1@21.264,5.456 R36.2@21.964,5.456 22.342,5.456 22.429,5.543 22.635,5.543 22.683,5.592 22.693,5.592 22.719,5.617 23.221,5.617 23.339,5.5 23.339,4.677 ; R43.1@22.532,9.785 R43.1@22.566,9.75 ; v1(22.604,9.345) 22.566,9.383 R43.1@22.566,9.75 ; v1(22.959,3.568) 22.959,4.035 ; v1@22.989,3.568 22.959,3.598 22.959,4.035 ; C49.2@23.232,9.785 22.566,9.785 R43.1@22.566,9.75 ; R35.2@26.269,6.006 26.621,6.006 26.84,5.787 26.84,5.496 26.971,5.365 ; 27.75,5.234 27.101,5.234 26.971,5.365 ; 22.959,4.035 22.959,4.298 23.339,4.677 ; 23.339,4.677 23.458,4.797 25.831,4.797 25.913,4.878 26.484,4.878 26.971,5.365
  TOP w0.25: v1(3.468,17.722) 3.536,17.654 R2.2@3.536,17.27 ; v1(15.275,4.14) 15.275,4.293 15.871,4.889 16.429,4.889 16.651,5.111 16.651,5.797 16.443,6.006 C39.2@16.229,6.006 R16.2@15.529,6.006 ; v1(23.661,16.141) 23.69,16.112 24.172,16.112 24.201,16.141 C26.2@24.277,16.065 ; C6.2@26.976,17.131 27.482,17.131 27.727,16.886 27.811,16.886 C23.2@27.841,16.856 ; v1(27.902,16.133) 27.841,16.195 C23.2@27.841,16.856 ; U1.B2@28.302,15.03 28.329,15.03 28.478,14.881 28.604,14.881 v1(28.633,14.853) ; U1.H4@29.902,10.23 29.89,10.242 29.89,10.767 29.902,10.779 U1.G4@29.902,11.03 29.922,11.049 29.922,11.135 29.957,11.171 29.957,11.546 29.922,11.582 29.922,11.811 U1.F4@29.902,11.83 U1.E4@29.902,12.63 29.929,12.63 30.017,12.717 30.153,12.717 30.652,13.217 30.652,13.353 30.712,13.413 31.009,13.413 31.052,13.37 v1(31.092,13.37) ; v1@31.109,13.354 31.136,13.381 31.252,13.381 31.282,13.411 31.464,13.411 31.493,13.44 31.493,13.415 31.896,13.012 v1(31.896,12.98) ; v1@31.897,12.979 31.927,12.979 32.275,12.63 U1.E7@32.302,12.63 ; v1(31.949,16.388) 31.949,16.429 32.041,16.52 C18.2@32.041,16.856 ; U1.G7@32.302,11.03 32.655,11.382 ; 32.652,11.385 32.655,11.382 ; v1(32.672,3.218) 33.07,3.615 33.07,4.104 34.223,5.258 34.223,5.712 L1.1@34.204,5.731 ; U1.D9@33.902,13.43 33.923,13.43 v1(34.289,13.064) 34.289,13.04 33.902,12.654 U1.E9@33.902,12.63 33.902,11.99 U1.F9@33.902,11.83 33.883,11.849 33.77,11.849 33.684,11.935 33.278,11.935 33.223,11.88 33.179,11.88 33.129,11.83 U1.F8@33.102,11.83 32.655,11.382 ; C7.2@34.141,16.856 C18.2@32.041,16.856 ; v1(34.872,17.669) 34.9,17.64 34.9,17.242 C21.2@35.009,17.133 ; R20.2@41.5,16.004 41.501,16.005 R40.2@42.2,16.006 R40.2@42.2,16.006 42.464,16.006 42.651,16.193 42.651,16.303 v1(42.68,16.332) ; R1.2@42.2,17.406 42.204,17.401 42.632,17.401 v1(42.636,17.397) ; C23.2@27.841,16.856 C18.2@32.041,16.856
  TOP w0.3: C48.2@16.661,11.43 16.661,10.508 16.626,10.472 C37.2@16.656,10.472 C36.2@17.554,10.472 ; C36.2@17.584,10.472 17.596,10.485 18.004,10.485 18.047,10.528 v1(18.074,10.528) ; L7.2@22.241,15.998 22.857,15.998 22.897,16.038 v1(22.924,16.038) ; U1.H6@31.502,10.23 31.502,10.225 31.839,9.889 v1(31.839,9.884) ; v1@31.907,9.826 U1.J7@32.302,9.43 ; U1.J7@32.316,9.43 32.503,9.243 32.887,9.243 33.064,9.42 33.089,9.42 U1.J8@33.1,9.432
  TOP w0.35: J2.2@38.039,10.93 39.308,10.93 39.916,10.323 v1(39.916,9.866)
  TOP w0.5: v1(12.689,12.875) 12.698,12.884 v1(13.209,12.884) ; v1@13.213,12.88 v1@13.76,12.88 ; v1@13.262,12.884 v1(13.209,12.884) ; L5.2@13.472,12.211 L5.2@13.797,11.886 ; L5.2@13.829,11.886 L5.2@13.797,11.886 ; v1(13.209,12.884) 13.209,12.211 13.534,11.886 L5.2@13.797,11.886
  L4_PWR w0.5: 5.27,3.81 7.508,3.81
  BOTTOM w0.35: 1.X@39.263,8.89 39.263,8.993 39.906,9.636 39.906,9.856 v1(39.916,9.866)
  other v1: 13.764,12.884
